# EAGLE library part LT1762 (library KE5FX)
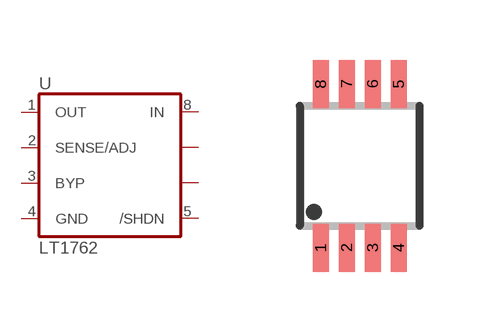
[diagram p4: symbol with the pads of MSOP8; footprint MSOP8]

Designator prefix U

## LT1762  [MSOP8]
1  OUT  pas
2  SENSE/ADJ  pas
3  BYP  pas
4  GND  pwr
5  /SHDN  pas
6    nc
7    nc
8  IN  pwr

## Footprint MSOP8 (pad centres in mm)
smd 0.4 x 1.2: 1 -0.975,-2.05; 2 -0.325,-2.05; 3 0.325,-2.05; 4 0.975,-2.05; 5 0.975,2.05; 6 0.325,2.05; 7 -0.325,2.05; 8 -0.975,2.05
